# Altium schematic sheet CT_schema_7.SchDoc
size 368 x 245 mm
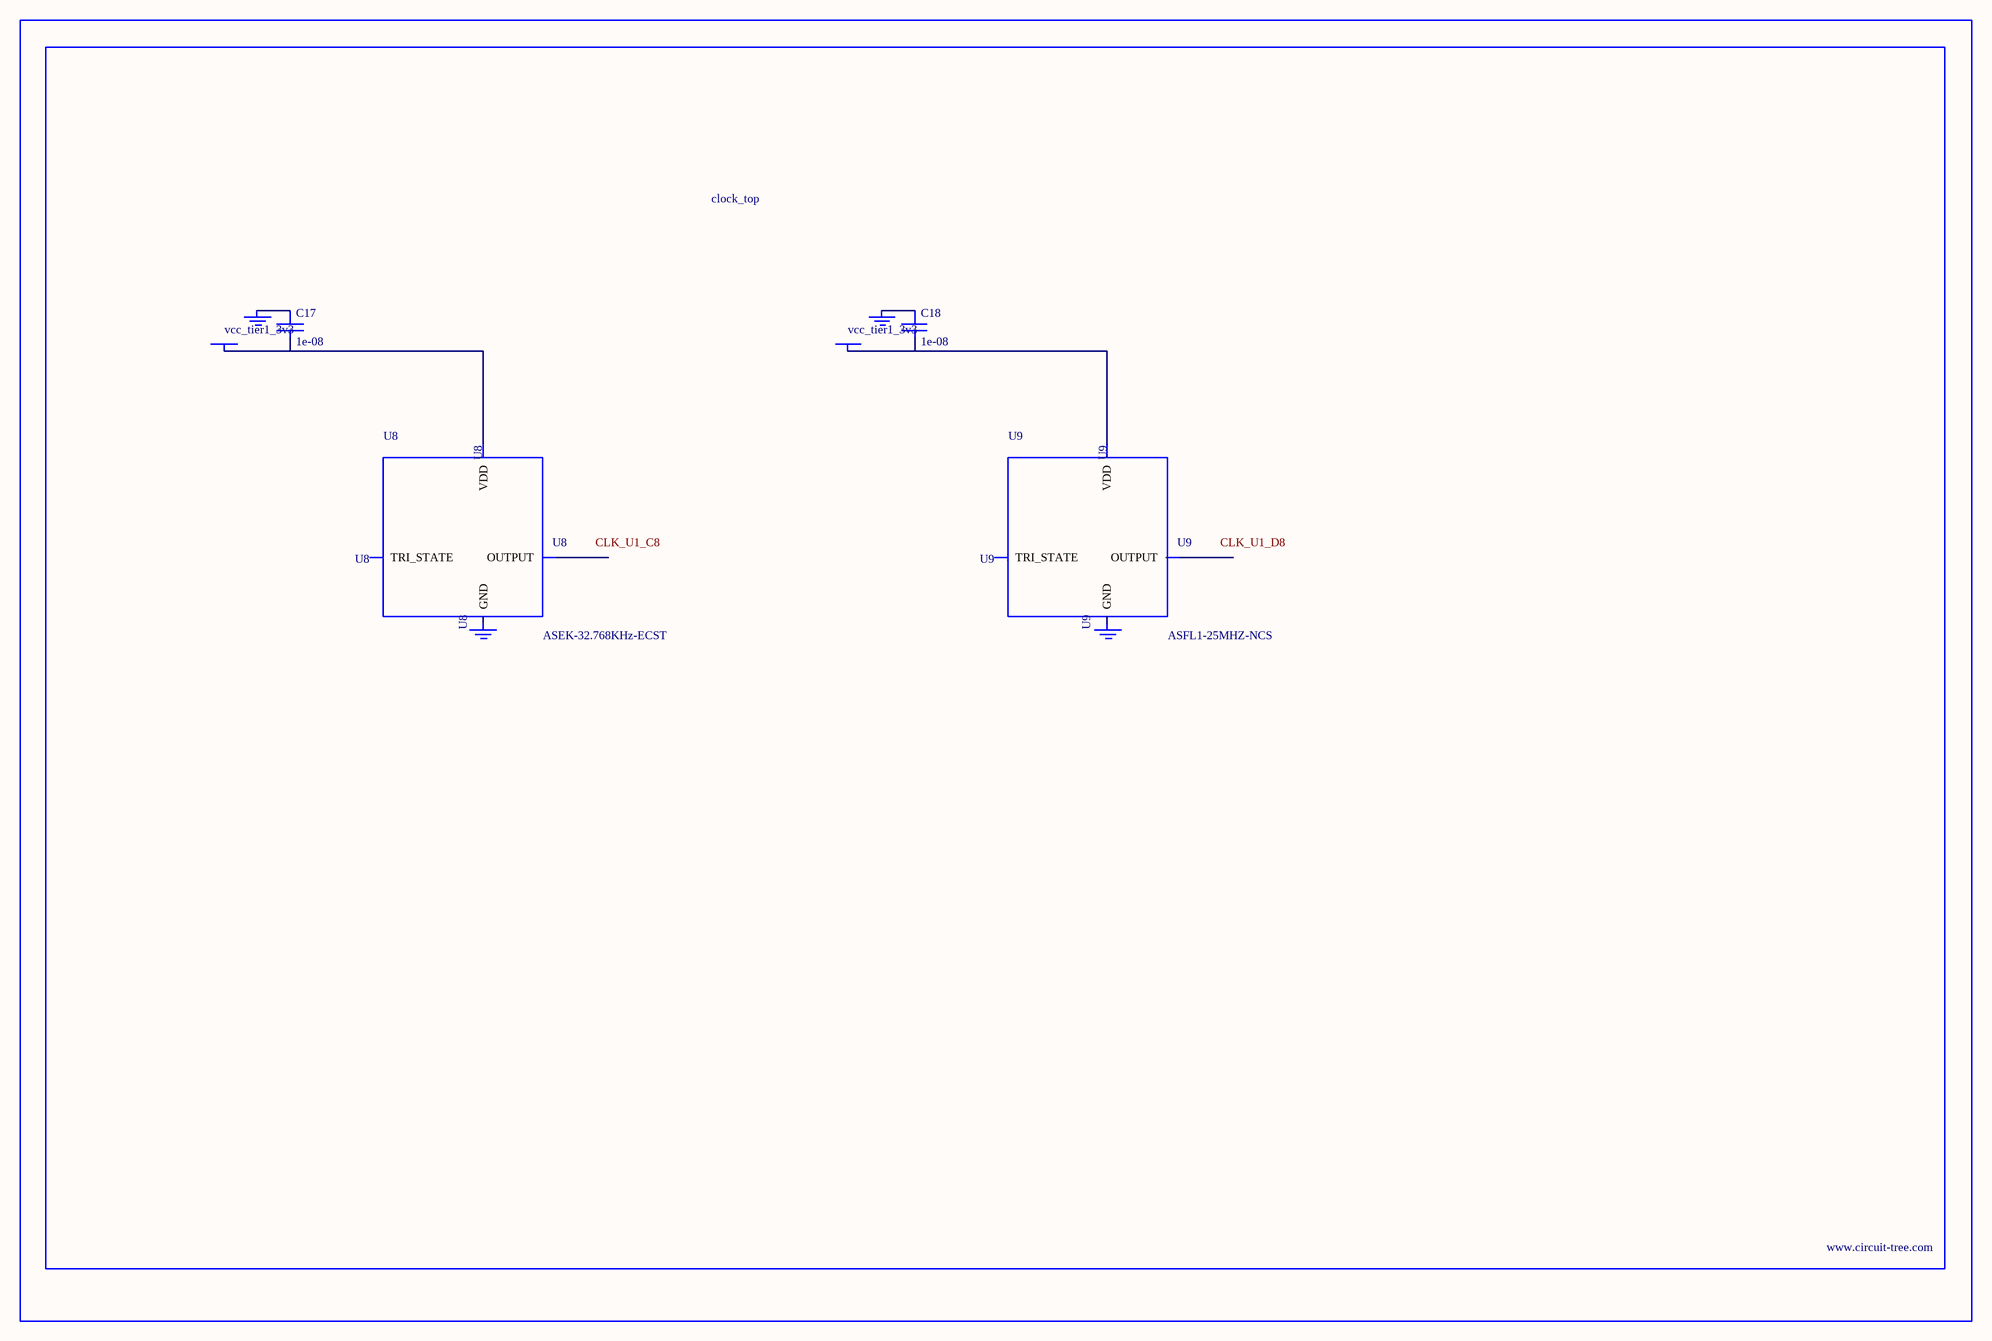
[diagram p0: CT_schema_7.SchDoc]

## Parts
BORDER6  (no value)
C17  1e-08  [C0402]
C18  1e-08  [C0402]
GND_INSTANCE_6_0  (no value)
GND_INSTANCE_6_1  (no value)
GND_INSTANCE_6_2  (no value)
GND_INSTANCE_6_3  (no value)
POWER_INSTANCE_6_0  vcc_tier1_3v3
POWER_INSTANCE_6_1  vcc_tier1_3v3
U8  ASEK-32.768KHz-ECST  [ASEK]
U9  ASFL1-25MHZ-NCS  [ASFL1]

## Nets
NetC17_1: C17.1 GND_INSTANCE_6_0.0(GND)
NetC17_2: C17.2 POWER_INSTANCE_6_0.0(PWR) U8.4(VDD)
NetC18_1: C18.1 GND_INSTANCE_6_2.0(GND)
NetC18_2: C18.2 POWER_INSTANCE_6_1.0(PWR) U9.4(VDD)

Not connected (* = marked no-connect by the designer): GND_INSTANCE_6_1 0(GND); GND_INSTANCE_6_3 0(GND); U8 1(TRI_STATE) 2(GND) 3(OUTPUT); U9 1(TRI_STATE) 2(GND) 3(OUTPUT)

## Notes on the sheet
- Labels drawn without touching a wire or pin: CLK_U1_C8, CLK_U1_D8

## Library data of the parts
BORDER6 = BORDER_PAGE6
C17 C18 = C0402C103K3RAC
GND_INSTANCE_6_0-GND_INSTANCE_6_3 = GND
POWER_INSTANCE_6_0 POWER_INSTANCE_6_1 = PWR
